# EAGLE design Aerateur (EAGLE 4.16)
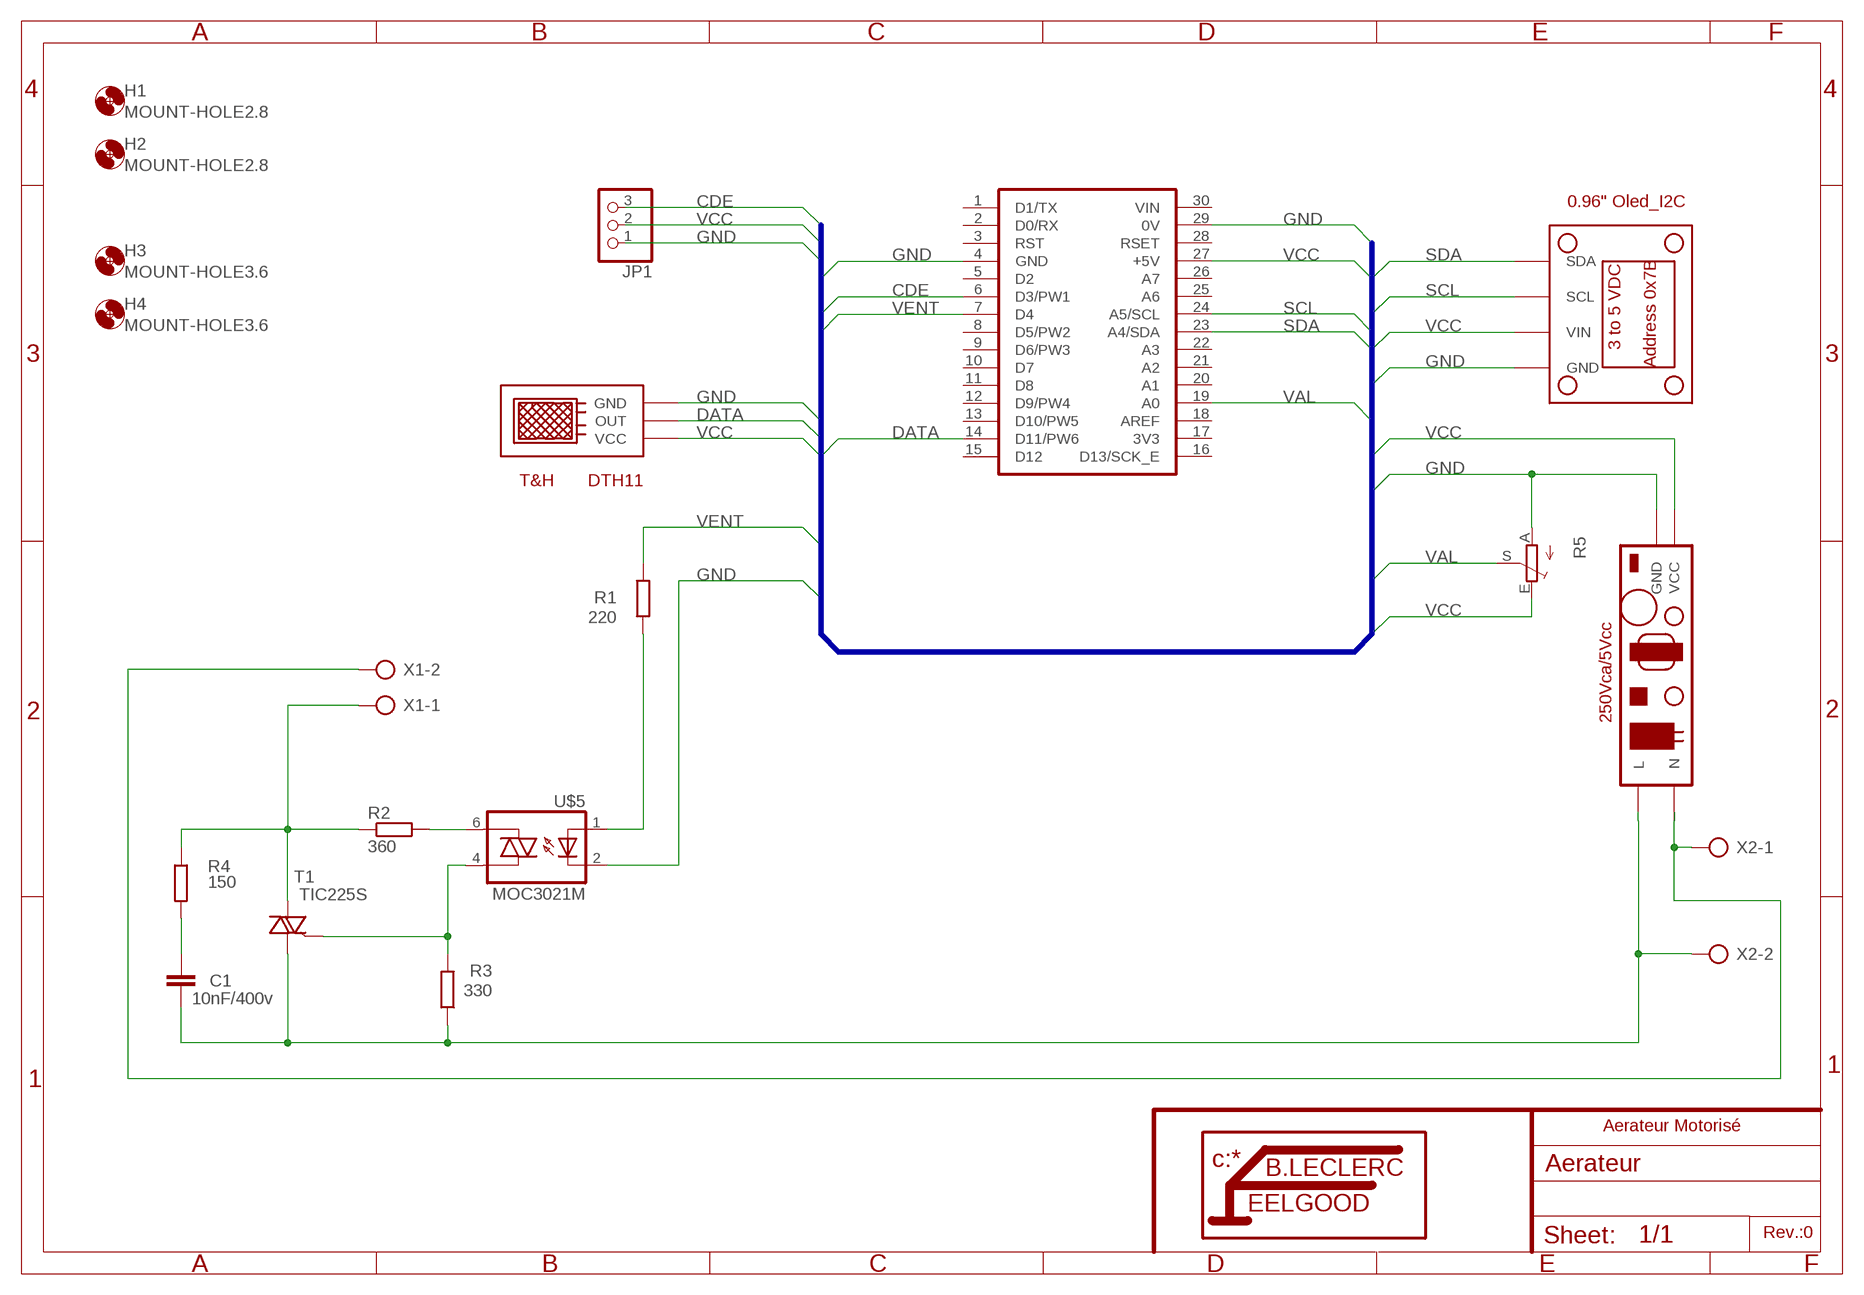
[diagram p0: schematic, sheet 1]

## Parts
C1  10nF/400v  C-EU075-032X103  [C075-032X103]
H1  MOUNT-HOLE2.8  [2,8]
H2  MOUNT-HOLE2.8  [2,8]
H3  MOUNT-HOLE3.6  [3,6]
H4  MOUNT-HOLE3.6  [3,6]
JP1  PINHD-1X3  [1X03]
R1  220  R-EU_0309/12  [0309/12]
R2  360  R-EU_0309/12  [0309/12]
R3  330  R-EU_0309/12  [0309/12]
R4  150  R-EU_0309/12  [0309/12]
R5  TRIM_EU-S63S  [S63S]
T1  TIC225S  [TO220DS]
U1  NANO  [NANO]
U$2  SWPWR250-5ALIM  [SWPWR250-5ALIM]
U$3  OLED_I2C_DISPLAY  [OLED_I2C_DISPLAY]
U$4  DTH11  [DTH11]
U$5  MOC3021M  [DIL06]
X1  AK300/2  [AK300/2]
X2  AK300/2  [AK300/2]

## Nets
CDE: JP1.3 U1.6(D3/PW1)
DATA: U1.14(D11/PW6) U$4.OUT
GND: JP1.1 R5.A U1.4(GND) U1.29(0V) U$2.GND U$3.GND U$4.GND U$5.2(C)
N$1: R1.1 U$5.1(A)
N$2: C1.1 R4.2
N$4: C1.2 R3.1 T1.A1 U$2.L X2.2
N$5: R3.2 T1.G U$5.4(A1)
N$6: R2.2 U$5.6(A2)
N$7: R2.1 R4.1 T1.A2 X1.1
N$9: U$2.N X1.2 X2.1
SCL: U1.24(A5/SCL) U$3.SCL
SDA: U1.23(A4/SDA) U$3.SDA
VAL: R5.S U1.19(A0)
VCC: JP1.2 R5.E U1.27(+5V) U$2.VCC U$3.VIN U$4.VCC
VENT: R1.2 U1.7(D4)
Unconnected: U1.1(D1/TX) U1.2(D0/RX) U1.3(RST) U1.5(D2) U1.8(D5/PW2) U1.9(D6/PW3) U1.10(D7) U1.11(D8) U1.12(D9/PW4) U1.13(D10/PW5) U1.15(D12) U1.16(D13/SCK_E) U1.18(AREF) U1.20(A1) U1.21(A2) U1.22(A3) U1.25(A6) U1.26(A7) U1.28(RSET)

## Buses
B$1

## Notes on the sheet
- Aerateur Motorisé
- Rev.:0

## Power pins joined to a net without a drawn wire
3V3: U1.17(3V3)
VIN: U1.30(VIN)

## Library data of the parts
C1 = rcl:C-EU: CAPACITOR, European symbol
H1-H4 = holes:MOUNT-HOLE: MOUNTING HOLE with drill center marker
JP1 = pinhead:PINHD-1X3: PIN HEADER
R1-R4 = rcl:R-EU_: RESISTOR, European symbol
R5 = pot:TRIM_EU-: POTENTIOMETER
T1 = triac:TIC225S: TRIAC
U1 = Arduino:NANO
U$2 = Arduino:SWPWR250-5ALIM
U$3 = Arduino:OLED_I2C_DISPLAY
U$4 = Arduino:DTH11
U$5 = optocoupler:MOC30*M: RANDOM-PHASE OPTOISOLATORS TRIAC DRIVER OUTPUT Source: http://www.fairchildsemi.com MOC3020-M.pdf
X1 X2 = con-ptr500:AK300/2: CONNECTOR

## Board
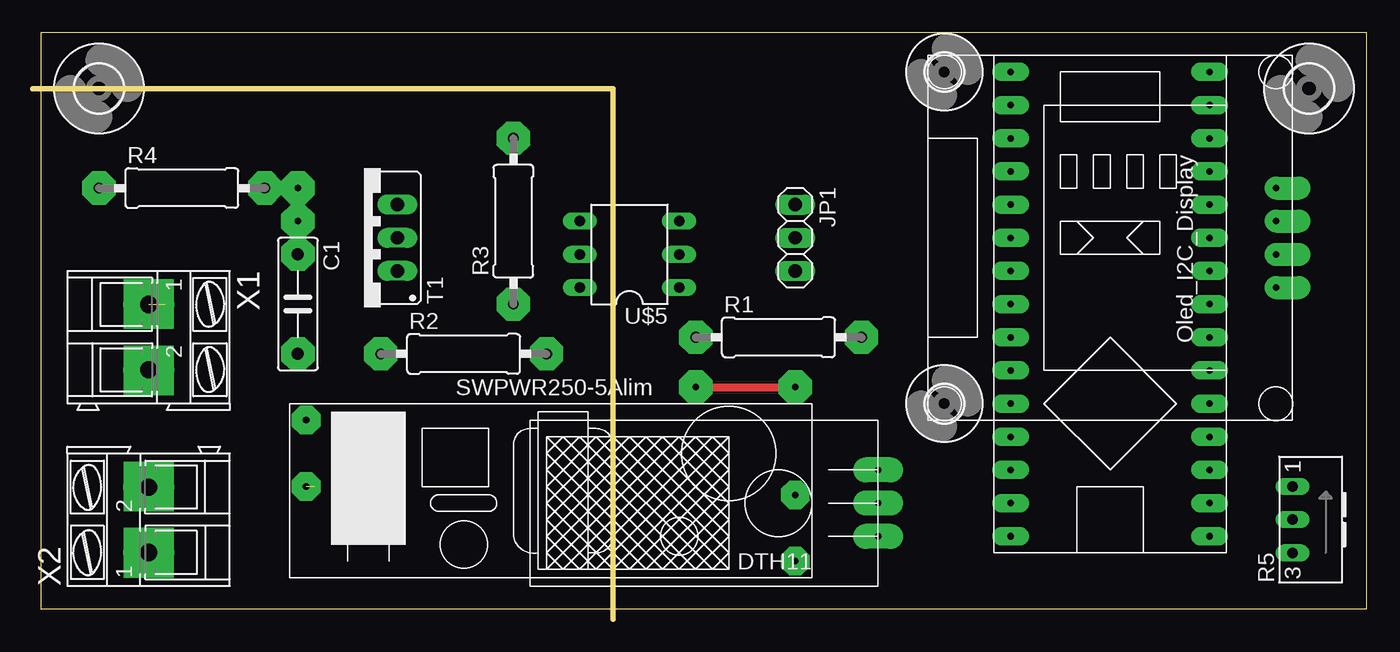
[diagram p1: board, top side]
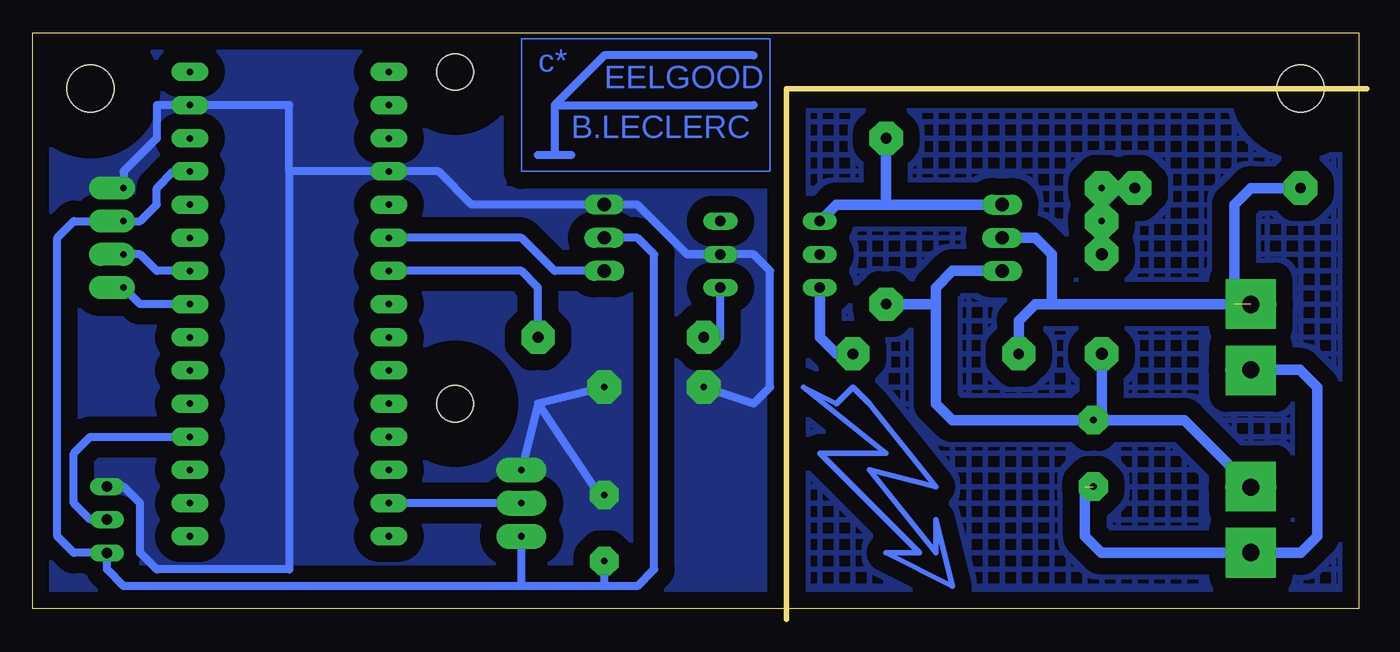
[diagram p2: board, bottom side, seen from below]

Size 102.22 x 44.92 mm. Coordinates in mm from the lower left corner, seen from the top.
Outline: 0,40.64 44.45,40.64 44.45,0
Outline: 0.64,0.8 102.22,0.8 102.22,44.92 0.64,44.92 0.64,0.8
Copper layers (1*16): Top 0.035mm / dielectric 1.5mm / Bottom 0.035mm
Design rules "default": minimum track width 10mil, minimum drill 24mil, track to track 8mil, track to pad 8mil, pad to pad 8mil, via to via 8mil, smd to smd 8mil, copper to edge 40mil, drill to drill 8mil, minimum pad ring 10mil, minimum via ring 8mil, stop-mask expansion 4mil, vias tented up to drill 0mil, thermal gap 10mil

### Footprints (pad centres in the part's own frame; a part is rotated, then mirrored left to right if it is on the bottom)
C075-032X103 = drill 0.914 octagon: 1 -3.81,0; 2 3.81,0
2,8 = hole 2.8: 0,0
3,6 = hole 3.6: 0,0
1X03 = drill 1.016 long: 1 -2.54,0; 2 0,0; 3 2.54,0
0309/12 = drill 0.813 octagon: 1 -6.35,0; 2 6.35,0
S63S = drill 0.813 long: A 2.54,1.27; E -2.54,1.27; S 0,1.27
TO220DS = drill 1.016 long: A1 -2.54,-2.54; A2 0,-2.54; G 2.54,-2.54
NANO = drill 0.5 pad 1.422 long: 1 -7.62,17.78; 2 -7.62,15.24; 3 -7.62,12.7; 4 -7.62,10.16; 5 -7.62,7.62; 6 -7.62,5.08; 7 -7.62,2.54; 8 -7.62,0; 9 -7.62,-2.54; 10 -7.62,-5.08; 11 -7.62,-7.62; 12 -7.62,-10.16; 13 -7.62,-12.7; 14 -7.62,-15.24; 15 -7.62,-17.78; 16 7.62,-17.78; 17 7.62,-15.24; 18 7.62,-12.7; 19 7.62,-10.16; 20 7.62,-7.62; 21 7.62,-5.08; 22 7.62,-2.54; 23 7.62,0; 24 7.62,2.54; 25 7.62,5.08; 26 7.62,7.62; 27 7.62,10.16; 28 7.62,12.7; 29 7.62,15.24; 30 7.62,17.78
SWPWR250-5ALIM = drill 0.5 pad 2.184 octagon: GND 19.05,-0.635; L -18.415,5.08; N -18.415,0; VCC 19.05,-5.715
OLED_I2C_DISPLAY = drill 0.5 pad 1.778 offset: GND 10.16,26.67; SCL 15.24,26.67; SDA 17.78,26.67; VIN 12.7,26.67
DTH11 = drill 0.5 pad 1.93 long: GND -5.08,-2.54; OUT -5.08,0; VCC -5.08,2.54
DIL06 = drill 0.813 long: 1 -2.54,-3.81; 2 0,-3.81; 3 2.54,-3.81; 4 2.54,3.81; 5 0,3.81; 6 -2.54,3.81
AK300/2 = drill 1.321 long: 1 -2.515,0; 2 2.489,0

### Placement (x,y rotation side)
C1  20.32,24.13 270 top
H1  69.85,41.91 0 top
H2  69.85,16.51 0 top
H3  5.08,40.64 0 top
H4  97.79,40.64 0 top
JP1  58.42,29.21 270 top
R1  57.15,21.59 0 top
R2  33.02,20.32 0 top
R3  36.83,30.48 90 top
R4  11.43,33.02 0 top
R5  97.79,7.62 90 top
T1  25.4,29.21 90 top
U1  82.55,24.13 0 top
U$2  39.37,10.16 0 top
U$3  68.58,43.18 270 top
U$4  59.69,8.89 180 top
U$5  45.72,27.94 90 top
U$6  [LITTFEEL]  62.23,31.75 0 bottom
X1  8.89,21.59 270 top
X2  8.89,7.62 90 top

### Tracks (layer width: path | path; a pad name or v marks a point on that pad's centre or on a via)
CDE
  Bottom 0.61: U1.6 64.77,29.21 62.23,26.67 JP1.3
DATA
  Bottom 0.61: U$4.OUT U1.14
GND  (via drill 0.5 pad 1.27, 0.5 pad 2.54)
  Top 0.61: v50.8,17.78 v58.42,17.78
  Bottom 0.61: 52.07,27.94 55.88,31.75 JP1.1 68.58,31.75 71.12,34.29 U1.4 82.55,34.29 | 52.07,27.94 U$5.2 | 63.5,16.51 U$4.GND | 63.5,16.51 58.42,8.89 | R5.A 95.25,10.16 93.98,8.89 93.98,5.08 92.71,3.81 82.55,3.81 82.55,34.29 | 82.55,34.29 82.55,39.37 U1.29 92.71,39.37 92.71,36.83 95.25,34.29 U$3.GND | 52.07,27.94 46.99,27.94 45.72,26.67 45.72,17.78 46.99,16.51 v50.8,17.78 | v58.42,17.78 63.5,16.51
  other vias: 58.42,31.75 49.53,27.94 96.52,10.16
  pour Bottom (isolate 1.27, no thermals): 45.72,33.02 66.04,33.02 66.04,44.45 101.6,44.45 101.6,1.27 45.72,1.27
N$1
  Bottom 0.61: U$5.1 49.53,21.59 R1.1
N$2  (via drill 0.5 pad 2.54)
  Bottom 0.813: R4.2 19.05,33.02 20.32,31.75 v20.32,30.48 C1.1
N$3  (via drill 0.5 pad 3.81)
  other vias: 8.89,24.13
N$4
  Bottom 0.813: 20.32,15.24 U$2.L | 20.32,15.24 C1.2 | 33.02,24.13 R3.1 | 33.02,24.13 33.02,16.51 31.75,15.24 20.32,15.24 | T1.A1 31.75,26.67 33.02,25.4 33.02,24.13 | 20.32,15.24 13.97,15.24 8.89,10.16 X2.2
N$5
  Bottom 0.813: T1.G 36.83,31.75 | 36.83,31.75 40.64,31.75 U$5.4 | 36.83,31.75 R3.2
N$6
  Bottom 0.813: U$5.6 41.91,21.59 40.64,20.32 R2.2
N$7  (1 unrouted)
  Bottom 0.813: R4.1 8.89,33.02 10.16,31.75 10.16,24.13 | T1.A2 25.4,29.21 24.13,27.94 24.13,24.13 | X1.1 8.89,24.13 24.13,24.13 | 24.13,24.13 25.4,24.13 26.67,22.86 R2.1
N$8  (via drill 0.5 pad 3.81)
  other vias: 8.89,19.05
N$9  (1 unrouted)
  Bottom 0.813: 21.59,10.16 21.59,6.35 20.34,5.11 X2.1 8.89,5.08 5.08,5.08 3.81,6.35 3.81,17.78 5.13,19.1 X1.2
N$10  (via drill 0.5 pad 3.81)
  other vias: 8.89,10.16
N$11  (via drill 0.5 pad 3.81)
  other vias: 8.89,5.08
N$12  (via drill 0.5 pad 1.27)
  other vias: 41.91,30.48
N$13  (via drill 0.5 pad 1.27)
  other vias: 41.91,27.94
N$14  (via drill 0.5 pad 1.27)
  other vias: 41.91,25.4
N$15  (via drill 0.5 pad 1.27)
  other vias: 49.53,30.48
N$16
  pour Bottom (isolate 1.27, no thermals, hatched): 1.27,35.56 7.62,35.56 10.16,38.1 10.16,40.64 44.45,40.64 44.45,1.27 1.27,1.27
N$17  (via drill 0.5 pad 1.27)
  other vias: 49.53,25.4
N$18  (via drill 0.5 pad 1.27)
  other vias: 27.94,31.75
N$19  (via drill 0.5 pad 1.27)
  other vias: 27.94,29.21
N$20  (via drill 0.5 pad 1.27)
  other vias: 27.94,26.67
N$21  (via drill 0.5 pad 2.54)
  other vias: 20.32,33.02
N$22  (via drill 0.5 pad 1.27)
  other vias: 58.42,29.21
N$23  (via drill 0.5 pad 1.27)
  other vias: 58.42,26.67
N$25  (via drill 0.5 pad 1.27)
  other vias: 96.52,7.62
N$26  (via drill 0.5 pad 1.27)
  other vias: 96.52,5.08
N$27  (via drill 0.5 pad 2.54)
  other vias: 5.08,33.02
N$28  (via drill 0.5 pad 2.54)
  other vias: 17.78,33.02
N$29  (via drill 0.5 pad 2.54)
  other vias: 20.32,27.94
N$30  (via drill 0.5 pad 2.54)
  other vias: 20.32,20.32
N$31  (via drill 0.5 pad 2.54)
  other vias: 26.67,20.32
N$32  (via drill 0.5 pad 2.54)
  other vias: 39.37,20.32
N$33  (via drill 0.5 pad 2.54)
  other vias: 36.83,36.83
N$34  (via drill 0.5 pad 2.54)
  other vias: 36.83,24.13
N$35  (via drill 0.5 pad 2.54)
  other vias: 50.8,21.59
N$36  (via drill 0.5 pad 2.54)
  other vias: 63.5,21.59
N$37
  Bottom 0.406: 33.02,10.16 38.1,16.51 39.37,17.78 40.64,16.51 43.18,17.78 36.83,12.7 41.91,12.7 34.29,5.08 36.83,5.08 31.75,2.54 33.02,7.62 33.02,5.08 38.1,11.43 33.02,10.16
SCL
  Bottom 0.61: U1.24 92.71,26.67 93.98,27.94 U$3.SCL
SDA
  Bottom 0.61: U1.23 93.98,24.13 U$3.SDA
VAL
  Bottom 0.61: U1.19 97.79,13.97 99.06,12.7 99.06,8.89 97.79,7.62 R5.S
VCC
  Bottom 0.61: 58.42,2.54 U$2.VCC | 58.42,2.54 64.77,2.54 | 64.77,2.54 95.25,2.54 96.52,3.81 R5.E 99.06,5.08 100.33,6.35 100.33,29.21 99.06,30.48 U$3.VIN 93.98,30.48 92.71,31.75 92.71,33.02 91.44,34.29 U1.27 | 64.77,2.54 U$4.VCC | JP1.2 55.88,29.21 54.61,27.94 54.61,3.81 55.88,2.54 58.42,2.54
VENT
  Bottom 0.61: U1.7 64.77,26.67 63.5,25.4 R1.2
